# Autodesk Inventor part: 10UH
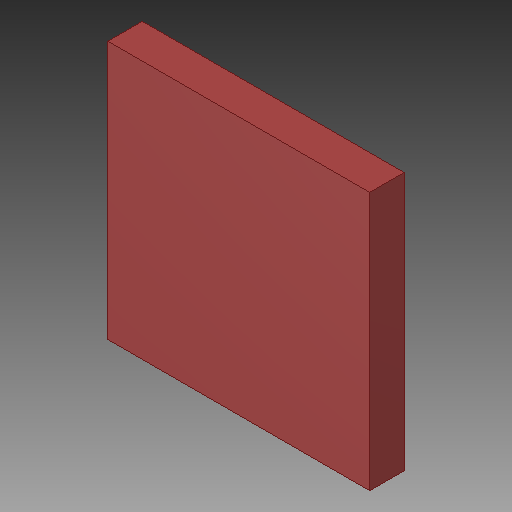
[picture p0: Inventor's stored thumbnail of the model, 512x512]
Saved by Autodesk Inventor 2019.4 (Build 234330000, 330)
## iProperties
Created: 2019-11
Part Number: 10UH
Material: Generic
Document SubType Name: Modeling
Designer: Willist
Density: 1 g/cm^3
Appearance: DR73, 10UH
Author: Willist
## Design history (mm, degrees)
sketch "DR73, 10UH_61"
  geometry: L1 (-3.802, 3.802)-(3.802, 3.802); L2 (3.802, 3.802)-(3.802, -3.7); L3 (3.802, -3.7)-(-3.802, -3.7); L4 (-3.802, -3.7)-(-3.802, 3.802)
  constraints: 8 end point
extrude "Extrusion1" join sketch "DR73, 10UH_61" distance "d0" = 1; taper "d1" = 0 deg
body "Solid1"
